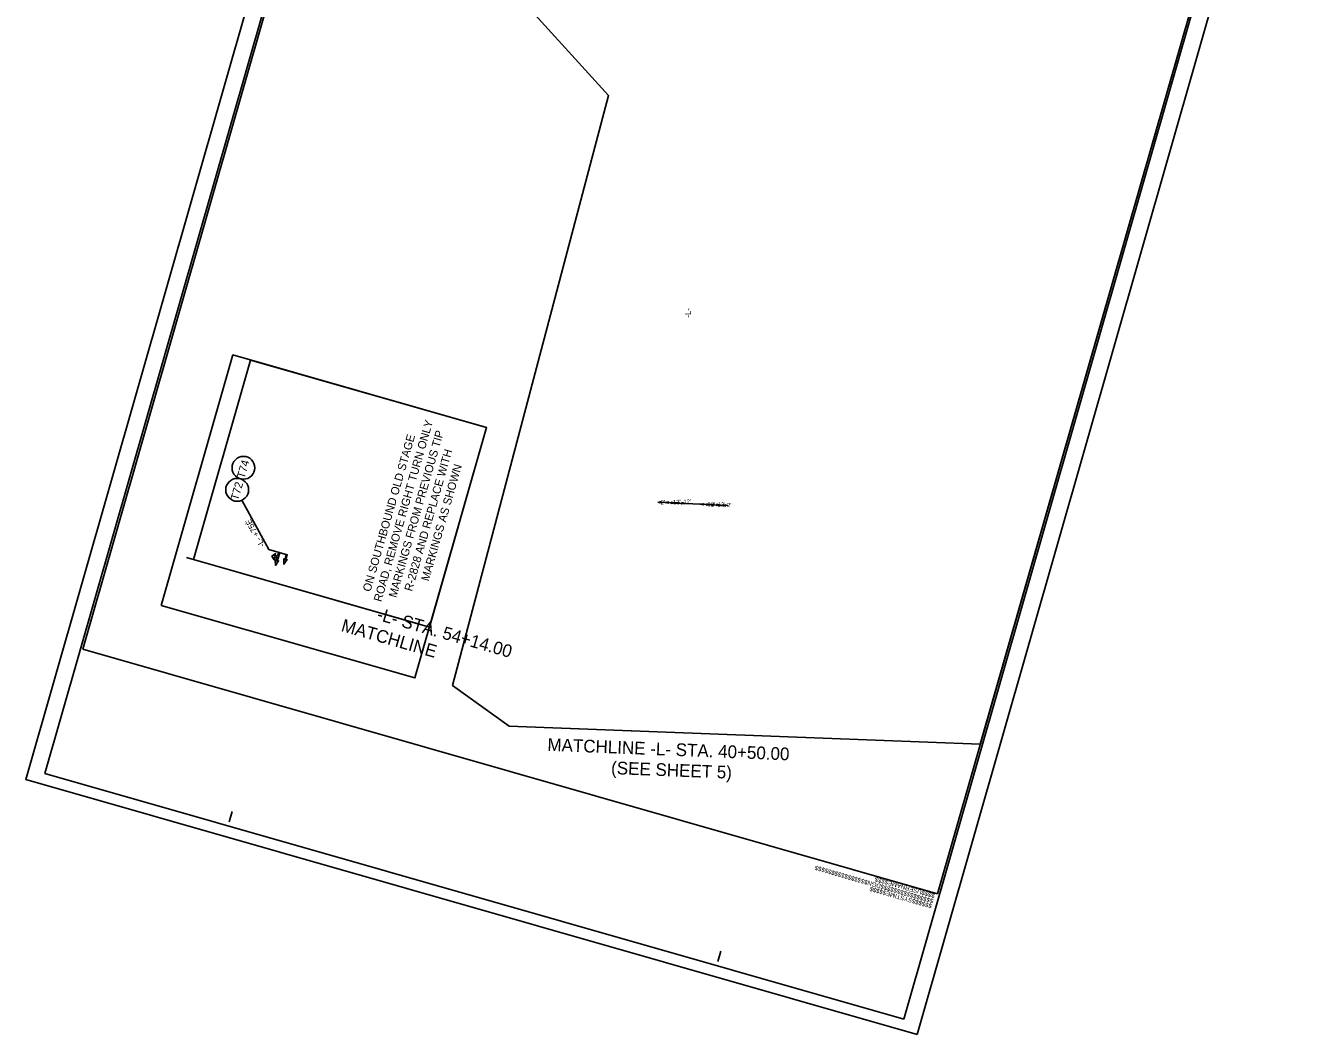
# Model space of a CAD drawing. Extents: x 2096990 to 2098506, y 687712 to 690186.
# Drawn here: x 2096990 to 2098506, y 687712 to 688904 of the extents above; entities that cross this region are included whole.
import ezdxf

# ---------------------------------------------------------------- set-up
doc = ezdxf.new("R2010")
doc.units = 0
for name, color, linetype in [('Default', 7, 'Continuous'), ('MARK STRAIGHT ARROW CELL', 7, 'Continuous'), ('MARK STRAIGHT RIGHT ARROW CELL', 7, 'Continuous'), ('Matchline', 7, 'Continuous'), ('Matchline Text', 7, 'Continuous'), ('Prop Horizontal Alignment Station Label', 7, 'Continuous'), ('Sheet Layout Plan Border', 7, 'Continuous'), ('Sheet Plan CELL', 7, 'Continuous'), ('Sheet Plot Border Inside CELL', 7, 'Continuous'), ('Sheet Plot Border Outside CELL', 7, 'Continuous'), ('Text', 7, 'Continuous')]:
    doc.layers.add(name, color=color, linetype=linetype)

msp = doc.modelspace()

# ---------------------------------------------------------------- linework, layer by layer
at = {"layer": 'Default'}
msp.add_line((2097819.7, 688336.7), (2097737.1, 688340.6), dxfattribs=at)
for points in [[(2097738.8, 688341.3), (2097743.3, 688340.4), (2097738.7, 688339.8), (2097739.3, 688340.5)], [(2097749.8, 688339.3), (2097745.3, 688340.2), (2097749.9, 688340.8), (2097749.3, 688340.1)], [(2097752.8, 688340.7), (2097757.3, 688339.7), (2097752.7, 688339.1), (2097753.3, 688339.9)], [(2097761.7, 688338.7), (2097757.2, 688339.7), (2097761.8, 688340.3), (2097761.2, 688339.5)], [(2097764.9, 688340.1), (2097769.4, 688339.1), (2097764.8, 688338.5), (2097765.4, 688339.3)], [(2097791.2, 688337.3), (2097786.7, 688338.2), (2097791.3, 688338.8), (2097790.7, 688338.1)], [(2097794.4, 688338.6), (2097798.8, 688337.6), (2097794.3, 688337.1), (2097794.9, 688337.8)], [(2097803.2, 688336.7), (2097798.7, 688337.7), (2097803.3, 688338.3), (2097802.6, 688337.5)], [(2097806.4, 688338.1), (2097810.8, 688337.1), (2097806.3, 688336.5), (2097806.9, 688337.3)], [(2097817.1, 688336), (2097812.7, 688337), (2097817.2, 688337.6), (2097816.6, 688336.8)]]:
    msp.add_lwpolyline(points, close=True, dxfattribs=at)
at = {"layer": 'MARK STRAIGHT ARROW CELL'}
msp.add_lwpolyline([(2097295.3, 688274), (2097296.3, 688272.4), (2097298.1, 688278.8), (2097299.3, 688278.5), (2097297.5, 688272), (2097299.1, 688272.9), (2097295.4, 688267.3)], close=True, dxfattribs=at)
msp.add_lwpolyline([(2097295.3, 688274), (2097296.3, 688272.4), (2097298.1, 688278.8), (2097299.3, 688278.5), (2097297.5, 688272), (2097299.1, 688272.9), (2097295.4, 688267.3)], close=True, dxfattribs=at)
at = {"layer": 'MARK STRAIGHT RIGHT ARROW CELL'}
msp.add_lwpolyline([(2097290.4, 688281), (2097287.4, 688270.6), (2097289.1, 688271.4), (2097285.4, 688265.8), (2097285.2, 688272.5), (2097286.2, 688270.9), (2097287.5, 688275.5), (2097286.8, 688275.2), (2097286.3, 688275.1), (2097285.7, 688275), (2097285.3, 688275), (2097284.7, 688275.1), (2097283.7, 688275.4), (2097283.7, 688272.5), (2097281.2, 688276.6), (2097285.6, 688279.9), (2097284.2, 688277.3), (2097285, 688277.1), (2097285.5, 688277), (2097286, 688277), (2097286.5, 688277.1), (2097286.9, 688277.2), (2097287.5, 688277.5), (2097287.9, 688278), (2097288.3, 688278.5), (2097288.5, 688279.1), (2097289.2, 688281.3)], close=True, dxfattribs=at)
msp.add_lwpolyline([(2097290.4, 688281), (2097287.4, 688270.6), (2097289.1, 688271.4), (2097285.4, 688265.8), (2097285.2, 688272.5), (2097286.2, 688270.9), (2097287.5, 688275.5), (2097286.8, 688275.2), (2097286.3, 688275.1), (2097285.7, 688275), (2097285.3, 688275), (2097284.7, 688275.1), (2097283.7, 688275.4), (2097283.7, 688272.5), (2097281.2, 688276.6), (2097285.6, 688279.9), (2097284.2, 688277.3), (2097285, 688277.1), (2097285.5, 688277), (2097286, 688277), (2097286.5, 688277.1), (2097286.9, 688277.2), (2097287.5, 688277.5), (2097287.9, 688278), (2097288.3, 688278.5), (2097288.5, 688279.1), (2097289.2, 688281.3)], close=True, dxfattribs=at)
at = {"layer": 'Matchline'}
for p, q in [((2097180.4, 688275.1), (2097454, 688196.8)), ((2097592.7, 688074.6), (2097942.4, 688061.2))]:
    msp.add_line(p, q, dxfattribs=at)
at = {"layer": 'Sheet Layout Plan Border'}
for points in [[(2098367.9, 688928.4), (2098117.8, 688054.5), (2097561.3, 688075.8), (2097494.5, 688123.8), (2097678.9, 688821), (2097441.6, 689082.4), (2097413, 689407.6), (2097643.8, 689341.5), (2097686.6, 689490.9), (2097794.8, 689516.3), (2097855.1, 689499), (2097840.3, 689446.6), (2098381.2, 689292.7), (2098283.8, 688952.5)], [(2097188.5, 688272.8), (2097256, 688508.5), (2097534.8, 688428.7), (2097467.3, 688193)]]:
    msp.add_lwpolyline(points, close=True, dxfattribs=at)
at = {"layer": 'Sheet Plan CELL'}
for p, q in [((2097470.6, 689609.1), (2097057.8, 688167)), ((2098067.3, 687878), (2098480.1, 689320.1)), ((2097057.8, 688167), (2098067.3, 687878)), ((2097230.9, 687963), (2097234.3, 687975)), ((2098067.3, 687878), (2098067.3, 687878)), ((2097807.7, 687797.9), (2097811.2, 687809.9))]:
    msp.add_line(p, q, dxfattribs=at)
msp.add_lwpolyline([(2097150.4, 688218.7), (2097235.1, 688514.5), (2097534.8, 688428.7), (2097450.1, 688132.9)], close=True, dxfattribs=at)
at = {"layer": 'Sheet Plot Border Inside CELL'}
msp.add_lwpolyline([(2098027.5, 687729.8), (2098485.9, 689331.4), (2097471.7, 689621.8), (2097013.2, 688020.1)], close=True, dxfattribs=at)
at = {"layer": 'Sheet Plot Border Outside CELL'}
msp.add_lwpolyline([(2098043.1, 687711.8), (2098506.4, 689330.3), (2097453.7, 689631.6), (2096990.4, 688013.1)], close=True, dxfattribs=at)
at = {"layer": 'Text'}
msp.add_lwpolyline([(2097299.3, 688278.5), (2097277.7, 688284.6), (2097245.7, 688342.9)], dxfattribs=at)
for centre in [(2097247.6, 688381.2), (2097240.2, 688355.2)]:
    msp.add_circle(centre, 13.5, dxfattribs=at)

# ---------------------------------------------------------------- texts
at = {"layer": 'Matchline Text'}
for s, rotation, p in [('-L- STA. 54+14.00', 343.9917, (2097404.2, 688201.8)), ('MATCHLINE ', 343.9917, (2097362, 688188.5)), ('MATCHLINE -L- STA. 40+50.00', 357.7373, (2097606.4, 688046.8)), ('(SEE SHEET 5)', 357.7373, (2097681.6, 688019.4))]:
    msp.add_text(s, height=15, rotation=rotation, dxfattribs=at).set_placement(p)
at = {"layer": 'Prop Horizontal Alignment Station Label'}
msp.add_text('-L-', height=7, rotation=88.3348, dxfattribs=at).set_placement((2097776, 688558.5))
at = {"layer": 'Sheet Plan CELL'}
for s, p in [('$$$$$$$$$$$$$$$$DGN$$$$$$$$$$$$$$$$', (2098062.9, 687871.4)), ('$$$$USERNAME$$$$', (2098064.7, 687877.7)), ('$$$$$$SYSTIME$$$$$', (2098061.3, 687865.5))]:
    msp.add_text(s, height=5.25, rotation=164.0259, dxfattribs=at).set_placement(p)
at = {"layer": 'Text'}
for s, height, rotation, p in [('ROAD, REMOVE RIGHT TURN ONLY', 9.66, 74.0259, (2097410.4, 688222.2)), ('ON SOUTHBOUND OLD STAGE', 9.66, 74.0259, (2097397.5, 688234.1)), ('MARKINGS FROM PREVIOUS TIP', 9.66, 74.0259, (2097428.1, 688227.1)), ('R-2828 AND REPLACE WITH', 9.66, 74.0259, (2097446.6, 688234.6)), ('T74', 9.45, 74.0259, (2097248.7, 688367.9)), ('MARKINGS AS SHOWN', 9.66, 74.0259, (2097466.4, 688246.6)), ('T72', 9.45, 74.0259, (2097241.3, 688342)), ("2'", 5, 2.3495, (2097740.4, 688337.8)), ("12'", 5, 2.3495, (2097755, 688338.1)), ("12'", 5, 2.3495, (2097767.3, 688338.5)), ("12'", 5, 358.5987, (2097795.6, 688335.6)), ("12'", 5, 358.5987, (2097807.6, 688335.4)), ("2'", 5, 358.5987, (2097818.7, 688334.8)), ('-L- +75È', 7, 118.8158, (2097273.1, 688289.9))]:
    msp.add_text(s, height=height, rotation=rotation, dxfattribs=at).set_placement(p)

doc.saveas('drawing.dxf')
